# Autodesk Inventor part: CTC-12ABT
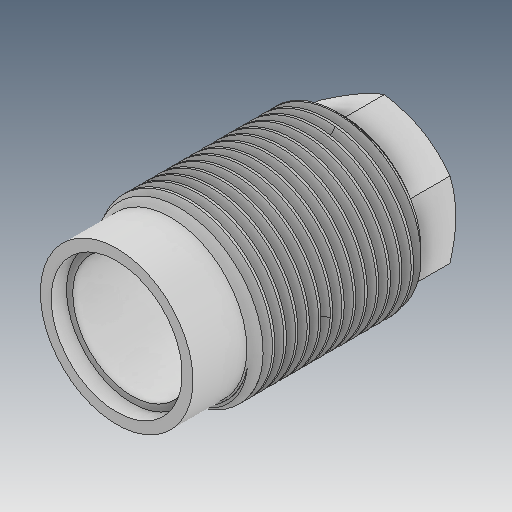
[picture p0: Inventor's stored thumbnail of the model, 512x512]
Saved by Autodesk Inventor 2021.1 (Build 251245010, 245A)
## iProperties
Created: 2010-01
Part Number: CTC-12ABT
Material: Ogólny
Document SubType Name: Modeling
Designer: user
Density: 1 g/cm^3
Appearance: Domyślna
Author: user
Revision Number: 1LAST_VERSION
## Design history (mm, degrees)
feature "Baza1"
node "Bryła1"
